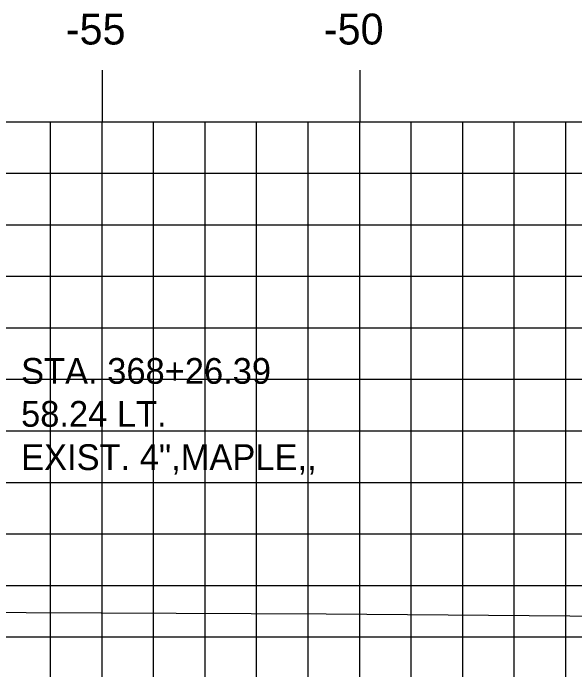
# Model space of a CAD drawing. Extents: x 1147855 to 1148025, y 608981 to 609091.
# Drawn here: x 1147881.48 to 1147892.39, y 609029.69 to 609042.44 of the extents above; entities that cross this region are included whole.
import ezdxf

# ---------------------------------------------------------------- set-up
doc = ezdxf.new("R2010")
doc.units = 0
for name, color, linetype in [('D_Text_Monospaced', 7, 'Continuous'), ('H_V ANNOTATION', 7, 'Continuous'), ('MAJOR', 7, 'Continuous'), ('MINOR', 7, 'Continuous'), ('S_Roadway_Centerline', 7, 'Continuous')]:
    doc.layers.add(name, color=color, linetype=linetype)

msp = doc.modelspace()

# ---------------------------------------------------------------- linework, layer by layer
at = {"layer": 'MAJOR'}
for p, q in [((1147883.211, 609041.337), (1147883.211, 609040.335)), ((1147888.211, 609041.337), (1147888.211, 609040.335)), ((1147868.211, 609040.335), (1148008.211, 609040.335)), ((1147868.211, 609040.335), (1148008.211, 609040.335)), ((1147883.211, 609020.335), (1147883.211, 609040.335)), ((1147888.211, 609020.335), (1147888.211, 609040.335)), ((1147868.211, 609035.335), (1148008.211, 609035.335)), ((1147868.211, 609030.335), (1148008.211, 609030.335))]:
    msp.add_line(p, q, dxfattribs=at)
at = {"layer": 'MINOR'}
for p, q in [((1147882.211, 609020.335), (1147882.211, 609040.335)), ((1147884.211, 609020.335), (1147884.211, 609040.335)), ((1147885.211, 609020.335), (1147885.211, 609040.335)), ((1147886.211, 609020.335), (1147886.211, 609040.335)), ((1147887.211, 609020.335), (1147887.211, 609040.335)), ((1147889.211, 609020.335), (1147889.211, 609040.335)), ((1147890.211, 609020.335), (1147890.211, 609040.335)), ((1147891.211, 609020.335), (1147891.211, 609040.335)), ((1147892.211, 609020.335), (1147892.211, 609040.335)), ((1147868.211, 609039.335), (1148008.211, 609039.335)), ((1147868.211, 609038.335), (1148008.211, 609038.335)), ((1147868.211, 609037.335), (1148008.211, 609037.335)), ((1147868.211, 609036.335), (1148008.211, 609036.335)), ((1147868.211, 609034.335), (1148008.211, 609034.335)), ((1147868.211, 609033.335), (1148008.211, 609033.335)), ((1147868.211, 609032.335), (1148008.211, 609032.335)), ((1147868.211, 609031.335), (1148008.211, 609031.335))]:
    msp.add_line(p, q, dxfattribs=at)
at = {"layer": 'S_Roadway_Centerline'}
msp.add_lwpolyline([(1147875.468, 609030.895), (1147878.817, 609030.82), (1147887.56, 609030.781), (1147903.328, 609030.651), (1147904.366, 609030.659), (1147905.033, 609030.646), (1147917.167, 609029.936)], dxfattribs=at)

# ---------------------------------------------------------------- texts
at = {"layer": 'D_Text_Monospaced'}
for s, height, p in [('STA. 368+26.39', 0.49998, (1147881.639, 609035.248)), ('58.24 LT.', 0.5, (1147881.639, 609034.414)), ('EXIST. 4",MAPLE,,', 0.49998, (1147881.639, 609033.574))]:
    msp.add_text(s, height=height, dxfattribs=at).set_placement(p)
at = {"layer": 'H_V ANNOTATION'}
for s, p in [('-55', (1147882.507, 609041.835)), ('-50', (1147887.515, 609041.835))]:
    msp.add_text(s, height=0.6, dxfattribs=at).set_placement(p)

doc.saveas('drawing.dxf')
